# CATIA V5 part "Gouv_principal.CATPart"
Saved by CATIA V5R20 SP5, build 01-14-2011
Part number: Skl_Gouv_principal
Publications: "Plan xy", "Axe_pivot_gouv/vol_ar", "Axe_pivot_gouv/vol_av&coque", "Axe_pivot_gouv/roulement&tambour"
Bounding box of the stored display mesh (mm): x 0 to 0, y 122.727 to 360, z -1100 to 240
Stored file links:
  U:\2A\CFAO\dossier sans titre\Gouv_principal.CATPart
  U:\2A\CFAO\dossier sans titre\Skl_gouvernail.CATProduct
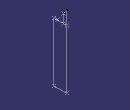
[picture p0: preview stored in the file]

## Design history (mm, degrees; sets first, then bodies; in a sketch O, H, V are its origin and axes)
Set1
  Point1 to Point5: linked copy from another document
  Point6 "Point.24": linked copy from another document
  Point7 "Point.23": linked copy from another document
Body1 (main body)
  Line1 "Axe_pivot_gouv/vol_av&coque": type PtPt, FirstPoint Point1, SecondPoint Point2, Start 250
  Line2: type PtPt, FirstPoint Point2, SecondPoint Point3
  Line3: type PtPt, FirstPoint Point1, SecondPoint Point5
  Line4 "Axe_pivot_gouv/vol_ar": type PtPt, FirstPoint Point5, SecondPoint Point3
  Line5 "Axe_pivot_gouv/roulement&tambour": type PtPt, FirstPoint Point6, SecondPoint Point7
